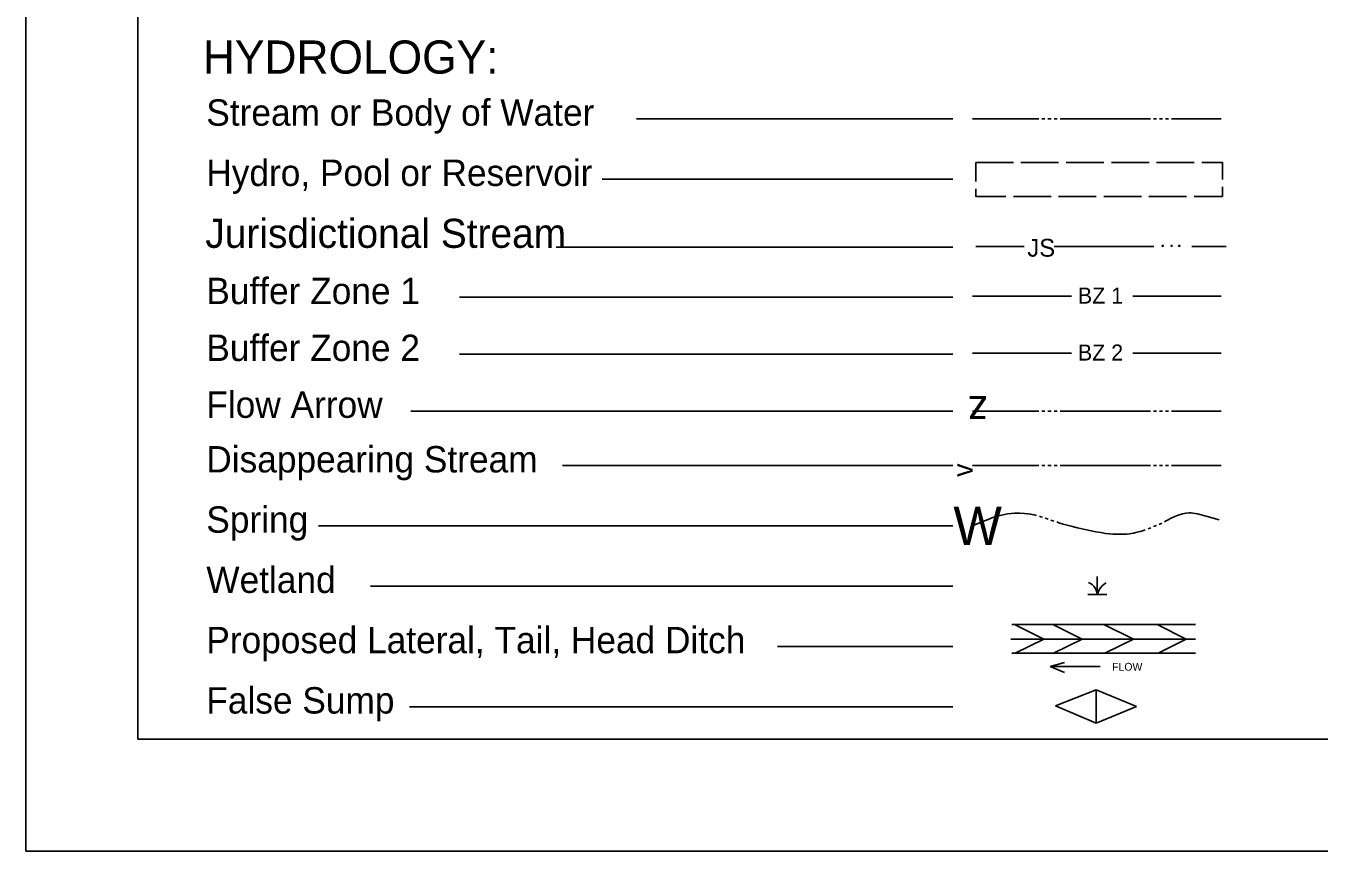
# Model space of a CAD drawing. Extents: x -0.53 to 3.34, y -0.27 to 4.33.
# Drawn here: x 0.217 to 0.939, y 2.495 to 2.956 of the extents above; entities that cross this region are included whole.
import ezdxf

# ---------------------------------------------------------------- set-up
doc = ezdxf.new("R2010")
doc.units = 0
for name, color, linetype in [('Sheet_Plan', 7, 'Continuous'), ('Sheet_Symbology', 7, 'Continuous'), ('z - Construction', 7, 'Continuous')]:
    doc.layers.add(name, color=color, linetype=linetype)

msp = doc.modelspace()

# ---------------------------------------------------------------- linework, layer by layer
at = {"layer": 'Sheet_Plan'}
for q in [(0.2799, 4.26594), (2.98819, 2.55761)]:
    msp.add_line((0.2799, 2.55761), q, dxfattribs=at)
at = {"layer": 'Sheet_Symbology'}
for p, q in [((0.73467, 2.90373), (0.5581, 2.90373)), ((0.74562, 2.90373), (0.78266, 2.90373)), ((0.78434, 2.90373), (0.78602, 2.90373)), ((0.7877, 2.90373), (0.78938, 2.90373)), ((0.79106, 2.90373), (0.79275, 2.90373)), ((0.79443, 2.90373), (0.84487, 2.90373)), ((0.84656, 2.90373), (0.84824, 2.90373)), ((0.84992, 2.90373), (0.8516, 2.90373)), ((0.85328, 2.90373), (0.85496, 2.90373)), ((0.85665, 2.90373), (0.88435, 2.90373)), ((0.74741, 2.87948), (0.76843, 2.87948)), ((0.74741, 2.86888), (0.74741, 2.87948)), ((0.77263, 2.87948), (0.79365, 2.87948)), ((0.79785, 2.87948), (0.81887, 2.87948)), ((0.82308, 2.87948), (0.8441, 2.87948)), ((0.8483, 2.87948), (0.86932, 2.87948)), ((0.73467, 2.8701), (0.53896, 2.8701)), ((0.7894, 2.86043), (0.76838, 2.86043)), ((0.81463, 2.86043), (0.79361, 2.86043)), ((0.83985, 2.86043), (0.81883, 2.86043)), ((0.86507, 2.86043), (0.84405, 2.86043)), ((0.73467, 2.8321), (0.51337, 2.8321)), ((0.73467, 2.80416), (0.45931, 2.80416)), ((0.74562, 2.80489), (0.80077, 2.80489)), ((0.88435, 2.80489), (0.83507, 2.80489)), ((0.73467, 2.77243), (0.45931, 2.77243)), ((0.74562, 2.77298), (0.80077, 2.77298)), ((0.88435, 2.77298), (0.83507, 2.77298)), ((0.73467, 2.7407), (0.43226, 2.7407)), ((0.74562, 2.7407), (0.78266, 2.7407)), ((0.78434, 2.7407), (0.78602, 2.7407)), ((0.7877, 2.7407), (0.78938, 2.7407)), ((0.79106, 2.7407), (0.79275, 2.7407)), ((0.79443, 2.7407), (0.84487, 2.7407)), ((0.84656, 2.7407), (0.84824, 2.7407)), ((0.84992, 2.7407), (0.8516, 2.7407)), ((0.85328, 2.7407), (0.85496, 2.7407)), ((0.85665, 2.7407), (0.88435, 2.7407)), ((0.73467, 2.71023), (0.51689, 2.71023)), ((0.74562, 2.71023), (0.78266, 2.71023)), ((0.78434, 2.71023), (0.78602, 2.71023)), ((0.7877, 2.71023), (0.78938, 2.71023)), ((0.79106, 2.71023), (0.79275, 2.71023)), ((0.79443, 2.71023), (0.84487, 2.71023)), ((0.84656, 2.71023), (0.84824, 2.71023)), ((0.84992, 2.71023), (0.8516, 2.71023)), ((0.85328, 2.71023), (0.85496, 2.71023)), ((0.85665, 2.71023), (0.88435, 2.71023)), ((0.78936, 2.67988), (0.79096, 2.67934)), ((0.73467, 2.6766), (0.38074, 2.6766)), ((0.84351, 2.67496), (0.84506, 2.67559)), ((0.84664, 2.6762), (0.84817, 2.67686)), ((0.81518, 2.63841), (0.81518, 2.64829)), ((0.73467, 2.64297), (0.40977, 2.64297)), ((0.80985, 2.63841), (0.82057, 2.63841)), ((0.76744, 2.62153), (0.87003, 2.62153)), ((0.76895, 2.62153), (0.78541, 2.61346)), ((0.79033, 2.62153), (0.80679, 2.61346)), ((0.81883, 2.62153), (0.83535, 2.61346)), ((0.84866, 2.62153), (0.8648, 2.61346)), ((0.767, 2.61346), (0.87003, 2.61346)), ((0.78541, 2.61346), (0.76941, 2.60564)), ((0.80679, 2.61346), (0.79085, 2.60564)), ((0.83535, 2.61346), (0.81942, 2.60564)), ((0.8648, 2.61346), (0.8491, 2.60564)), ((0.73467, 2.60934), (0.63684, 2.60934)), ((0.76744, 2.60564), (0.87003, 2.60564)), ((0.78888, 2.59807), (0.79695, 2.60034)), ((0.78888, 2.59807), (0.81688, 2.59807)), ((0.78888, 2.59807), (0.79695, 2.59479)), ((0.81463, 2.58515), (0.7918, 2.57628)), ((0.81463, 2.56657), (0.81463, 2.58515)), ((0.83701, 2.57586), (0.81463, 2.58515)), ((0.7918, 2.57628), (0.81463, 2.56657)), ((0.73467, 2.57571), (0.43152, 2.57571)), ((0.81463, 2.56657), (0.83701, 2.57586))]:
    msp.add_line(p, q, dxfattribs=at)
for points in [[(0.87352, 2.87948), (0.885, 2.87948), (0.885, 2.86993)], [(0.885, 2.86573), (0.885, 2.86043), (0.86928, 2.86043)], [(0.76418, 2.86043), (0.74741, 2.86043), (0.74741, 2.86468)], [(0.74741, 2.83244), (0.77432, 2.83244)], [(0.7912, 2.83244), (0.81478, 2.83244)], [(0.81478, 2.83244), (0.84673, 2.83244)], [(0.86791, 2.83244), (0.88711, 2.83244)], [(0.74564, 2.6766), (0.75041, 2.6786), (0.7552, 2.68062), (0.7564, 2.68108), (0.75853, 2.68182), (0.76017, 2.68226), (0.76262, 2.68282), (0.7651, 2.68327), (0.76719, 2.68352), (0.76904, 2.68367), (0.77065, 2.68371), (0.77208, 2.68371), (0.77458, 2.68356), (0.77646, 2.68337), (0.77784, 2.68316), (0.77992, 2.68276), (0.78135, 2.68243)], [(0.78299, 2.68198), (0.78377, 2.68175), (0.78459, 2.6815)], [(0.78619, 2.68097), (0.78688, 2.68074), (0.78778, 2.68043)], [(0.79256, 2.67879), (0.79384, 2.67835), (0.79619, 2.67765), (0.80071, 2.67646), (0.80412, 2.67559), (0.80922, 2.67442), (0.81437, 2.67334), (0.81723, 2.67284), (0.81976, 2.67246), (0.82198, 2.67221), (0.82394, 2.67204), (0.82564, 2.67196), (0.82715, 2.67192), (0.82976, 2.67196), (0.83172, 2.67208), (0.83319, 2.67225), (0.83535, 2.67257), (0.8375, 2.67303), (0.83911, 2.67347), (0.84052, 2.67389), (0.84193, 2.6744)], [(0.84973, 2.67751), (0.85007, 2.67765), (0.85126, 2.6782)], [(0.85278, 2.67896), (0.85358, 2.67936), (0.85688, 2.68108), (0.85856, 2.6819), (0.8603, 2.68261), (0.86163, 2.68306), (0.8628, 2.68335), (0.86385, 2.68356), (0.86478, 2.68371), (0.86642, 2.68381), (0.86764, 2.68381), (0.86854, 2.68375), (0.86989, 2.68356), (0.87121, 2.68327), (0.87718, 2.68163), (0.88313, 2.67997)], [(0.81518, 2.63841), (0.81492, 2.6396), (0.81458, 2.64078), (0.81399, 2.64187), (0.81323, 2.64289), (0.81239, 2.64382), (0.81138, 2.64449), (0.81028, 2.64508)], [(0.81518, 2.63841), (0.81568, 2.63968), (0.81627, 2.64095), (0.81703, 2.64213), (0.81796, 2.64314), (0.81897, 2.64407), (0.82007, 2.64491)]]:
    msp.add_lwpolyline(points, dxfattribs=at)
for centre in [(0.85167, 2.83291), (0.85665, 2.83291), (0.86099, 2.83291)]:
    msp.add_ellipse(centre, major_axis=(0, 0.000331), ratio=0.938496, dxfattribs=at)
at = {"layer": 'z - Construction'}
for p, q in [((0.2174, 4.32844), (0.2174, 2.49511)), ((0.2174, 2.49511), (3.05073, 2.49511))]:
    msp.add_line(p, q, dxfattribs=at)

# ---------------------------------------------------------------- texts
at = {"layer": 'Sheet_Symbology'}
for s, height, p in [('HYDROLOGY:', 0.018497, (0.31617, 2.929)), ('Stream or Body of Water', 0.0147137, (0.31808, 2.89993)), ('Hydro, Pool or Reservoir', 0.0147137, (0.31808, 2.8663)), ('Jurisdictional Stream', 0.0162204, (0.31752, 2.83177)), ('JS', 0.00993, (0.77619, 2.82685)), ('Buffer Zone 1', 0.0147137, (0.31808, 2.80036)), ('BZ 1', 0.008937, (0.80438, 2.80067)), ('Buffer Zone 2', 0.0147137, (0.31808, 2.76863)), ('BZ 2', 0.008937, (0.80438, 2.76889)), ('Flow Arrow', 0.014714, (0.31808, 2.7369)), ('Disappearing Stream', 0.0147137, (0.31808, 2.70643)), ('Spring', 0.014714, (0.31808, 2.6728)), ('W', 0.02144, (0.73492, 2.66588)), ('Wetland', 0.014714, (0.31808, 2.63917)), ('Proposed Lateral, Tail, Head Ditch', 0.0147137, (0.31808, 2.60554)), ('FLOW', 0.00436, (0.8235, 2.5958)), ('False Sump', 0.014714, (0.31808, 2.5719))]:
    msp.add_text(s, height=height, dxfattribs=at).set_placement(p)
for s, height, rotation, p in [('z', 0.01682, 180.00002, (0.75405, 2.74911)), ('v', 0.0111, 89.75915, (0.74562, 2.70395))]:
    msp.add_text(s, height=height, rotation=rotation, dxfattribs=at).set_placement(p)

doc.saveas('drawing.dxf')
